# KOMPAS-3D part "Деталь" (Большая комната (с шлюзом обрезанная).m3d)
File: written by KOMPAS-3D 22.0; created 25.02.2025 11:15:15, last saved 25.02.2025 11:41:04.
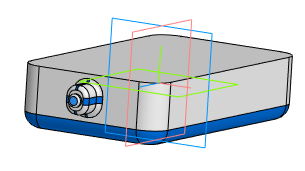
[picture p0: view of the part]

Document properties: Автор: Пользователь Windows; Полное имя файла: C:\Users\Student\Documents\Картошечка\База Сабнатика\Большая комната\Большая комната (с шлюзом обрезанная).m3d

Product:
- Body: Тело 1
    Масса: 2.227738
- Part/product: Деталь
    Масса: 1.809688

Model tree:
1. Эскиз:1
2. Элемент выдавливания:1
     Расстояние 1 = 35
3. Скругление:2  (with: Элемент выдавливания:1)
     Радиус = 10
4. Скругление:1  (with: Элемент выдавливания:1)
     Радиус = 7
5. Эскиз:2  (with: Элемент выдавливания:1)
6. Элемент выдавливания:2
     Расстояние 1 = 10
7. Скругление:3  (with: Элемент выдавливания:2)
     Радиус = 2
8. Эскиз:3  (with: Элемент выдавливания:2)
9. Элемент выдавливания:3
     Расстояние 1 = 2
10. Скругление:4  (with: Элемент выдавливания:3)
     Радиус = 1
11. Скругление:5  (with: Элемент выдавливания:2)
     Радиус = 2
12. Эскиз:4  (with: Элемент выдавливания:1)
13. Элемент выдавливания:4
     Расстояние 2 = 7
